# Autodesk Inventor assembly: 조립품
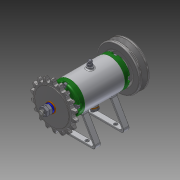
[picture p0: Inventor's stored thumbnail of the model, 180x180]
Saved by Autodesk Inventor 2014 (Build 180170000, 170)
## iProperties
Created: 2016-03
Part Number: 조립품
Document SubType Name: Assembly
Designer: basic
Author: basic
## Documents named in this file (16)
- C:\Users\basic\Desktop\460308V1027\조립품.iam
- C:\Users\basic\Desktop\460308V1027\본체.ipt
- C:\Users\basic\Desktop\460308V1027\베어링 15 x 32 x 9.ipt
- C:\Users\basic\Desktop\460308V1027\축.ipt
- C:\Users\basic\Desktop\460308V1027\커버.ipt
- C:\Users\basic\Desktop\460308V1027\오일 실 15 25 7.ipt
- C:\Users\basic\Desktop\460308V1027\스프로킷.ipt
- C:\Users\basic\Desktop\460308V1027\스프링와셔 8.ipt
- C:\Users\basic\Desktop\460308V1027\V벨트풀리.ipt
- C:\Users\basic\Desktop\460308V1027\와셔 8x17.ipt
- C:\Users\basic\Desktop\460308V1027\키 3 x 3 x 12.ipt
- C:\Users\basic\Desktop\460308V1027\너트 M 8.ipt
- C:\Users\basic\Desktop\460308V1027\니플 M 6 x 0.75.ipt
- C:\Users\basic\Desktop\460308V1027\와셔 6x11.5.ipt
- C:\Users\basic\Desktop\460308V1027\볼트 M 6 x 8.ipt
- C:\Users\basic\Desktop\460308V1027\볼트 M4 x 12.ipt
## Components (11 placed, 3 different names)
1. KS B 2023 6002 - 15 x 32 x 9:1
2. KS B 2023 6002 - 15 x 32 x 9:2
3. V벨트풀리:1
4. ISO 4762 M4 x 12:1
5. ISO 4762 M4 x 12:2
6. ISO 4762 M4 x 12:3
7. ISO 4762 M4 x 12:4
8. ISO 4762 M4 x 12:5
9. ISO 4762 M4 x 12:6
10. ISO 4762 M4 x 12:7
11. ISO 4762 M4 x 12:8
